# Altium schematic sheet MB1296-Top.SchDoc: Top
size A4; Date: 18-AUG-2016; Organization: STMicroelectronics; Address1: Microcontrollers Division; Address2: 190, avenue Célestin COQ; Address3: 13106 ROUSSET Cedex; Address4: FRANCE; DocumentNumber: MB1296; Revision: C-01; SheetNumber: 1; SheetTotal: 6; Project: STM32 LoRa Discovery
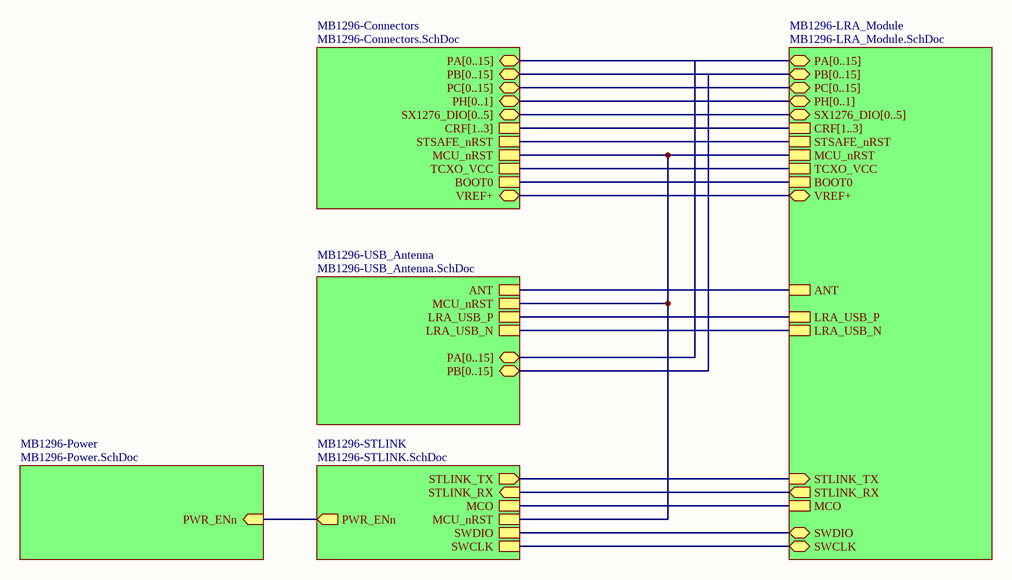
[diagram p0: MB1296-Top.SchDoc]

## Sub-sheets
MB1296-Connectors = MB1296-Connectors.SchDoc: PA[0..15] (bidir), PB[0..15] (bidir), PC[0..15] (bidir), MCU_nRST, BOOT0, SX1276_DIO[0..5] (bidir), CRF[1..3], TCXO_VCC, PH[0..1] (bidir), STSAFE_nRST, VREF+
MB1296-LRA_Module = MB1296-LRA_Module.SchDoc: LRA_USB_P, LRA_USB_N, STLINK_TX (in), STLINK_RX (out), ANT, STSAFE_nRST, MCU_nRST, TCXO_VCC, MCO, PA[0..15] (bidir), PB[0..15] (bidir), PC[0..15] (bidir), SX1276_DIO[0..5] (bidir), CRF[1..3], BOOT0, PH[0..1] (bidir), SWDIO, SWCLK, VREF+
MB1296-Power = MB1296-Power.SchDoc: PWR_ENn (in)
MB1296-STLINK = MB1296-STLINK.SchDoc: SWCLK, SWDIO, MCO, MCU_nRST, STLINK_RX (in), STLINK_TX (out), PWR_ENn (out)
MB1296-USB_Antenna = MB1296-USB_Antenna.SchDoc: LRA_USB_N, LRA_USB_P, MCU_nRST, ANT, PA[0..15] (bidir), PB[0..15] (bidir)

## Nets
(unnamed): sheet MB1296-Connectors/MCU_nRST, sheet MB1296-USB_Antenna/MCU_nRST, sheet MB1296-STLINK/MCU_nRST, sheet MB1296-LRA_Module/MCU_nRST
(unnamed): sheet MB1296-Connectors/BOOT0, sheet MB1296-LRA_Module/BOOT0  [a separate net that carries the same name]
(unnamed): sheet MB1296-Connectors/TCXO_VCC, sheet MB1296-LRA_Module/TCXO_VCC  [a separate net that carries the same name]
(unnamed): sheet MB1296-Connectors/STSAFE_nRST, sheet MB1296-LRA_Module/STSAFE_nRST  [a separate net that carries the same name]
(unnamed): sheet MB1296-Connectors/VREF+, sheet MB1296-LRA_Module/VREF+  [a separate net that carries the same name]
(unnamed): sheet MB1296-USB_Antenna/LRA_USB_N, sheet MB1296-LRA_Module/LRA_USB_N  [a separate net that carries the same name]
(unnamed): sheet MB1296-USB_Antenna/LRA_USB_P, sheet MB1296-LRA_Module/LRA_USB_P  [a separate net that carries the same name]
(unnamed): sheet MB1296-USB_Antenna/ANT, sheet MB1296-LRA_Module/ANT  [a separate net that carries the same name]
(unnamed): sheet MB1296-STLINK/SWCLK, sheet MB1296-LRA_Module/SWCLK  [a separate net that carries the same name]
(unnamed): sheet MB1296-STLINK/SWDIO, sheet MB1296-LRA_Module/SWDIO  [a separate net that carries the same name]
(unnamed): sheet MB1296-STLINK/MCO, sheet MB1296-LRA_Module/MCO  [a separate net that carries the same name]
(unnamed): sheet MB1296-STLINK/STLINK_RX, sheet MB1296-LRA_Module/STLINK_RX  [a separate net that carries the same name]
(unnamed): sheet MB1296-STLINK/STLINK_TX, sheet MB1296-LRA_Module/STLINK_TX  [a separate net that carries the same name]
(unnamed): sheet MB1296-STLINK/PWR_ENn, sheet MB1296-Power/PWR_ENn  [a separate net that carries the same name]

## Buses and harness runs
bus sheet MB1296-Connectors/CRF[1..3] = sheet MB1296-LRA_Module/CRF[1..3]
bus sheet MB1296-Connectors/PA[0..15] = sheet MB1296-LRA_Module/PA[0..15] = sheet MB1296-USB_Antenna/PA[0..15]
bus sheet MB1296-Connectors/PB[0..15] = sheet MB1296-LRA_Module/PB[0..15] = sheet MB1296-USB_Antenna/PB[0..15]
bus sheet MB1296-Connectors/PC[0..15] = sheet MB1296-LRA_Module/PC[0..15]
bus sheet MB1296-Connectors/PH[0..1] = sheet MB1296-LRA_Module/PH[0..1]
bus sheet MB1296-Connectors/SX1276_DIO[0..5] = sheet MB1296-LRA_Module/SX1276_DIO[0..5]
